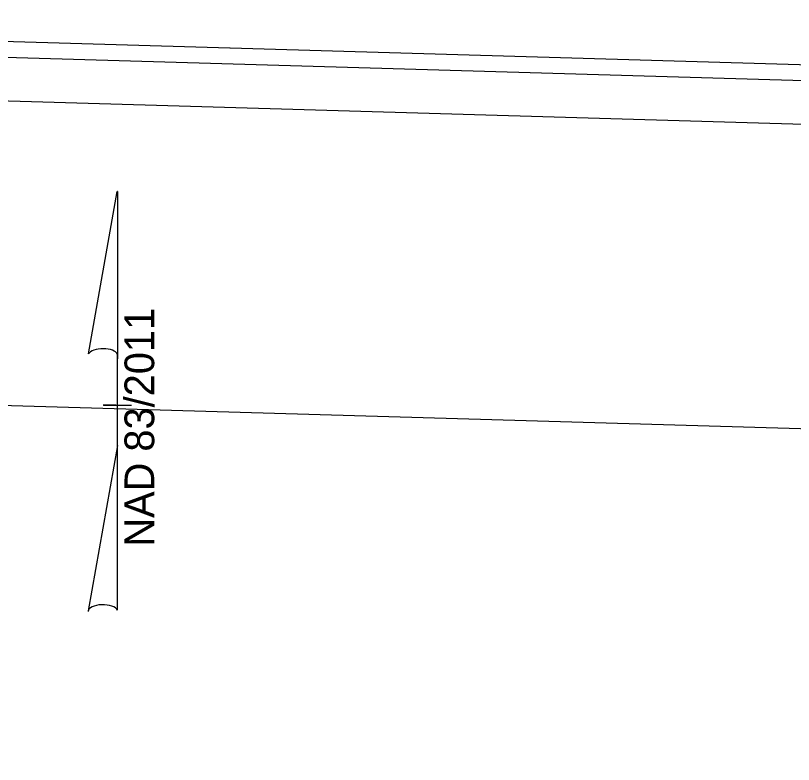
# Model space of a CAD drawing. Extents: x 2096999 to 2102576, y 682920 to 687015.
# Drawn here: x 2097306.6 to 2097529, y 686627 to 686841 of the extents above; entities that cross this region are included whole.
import ezdxf

# ---------------------------------------------------------------- set-up
doc = ezdxf.new("R2010")
doc.units = 0
for name, color, linetype in [('Default', 7, 'Continuous'), ('Scratch_Level_2', 7, 'Continuous'), ('Sheet Plan CELL', 7, 'Continuous'), ('Sheet Plot Border Inside CELL', 7, 'Continuous'), ('Sheet Plot Border Outside CELL', 7, 'Continuous')]:
    doc.layers.add(name, color=color, linetype=linetype)

msp = doc.modelspace()

# ---------------------------------------------------------------- linework, layer by layer
at = {"layer": 'Default'}
for p, q in [((2097327.5, 686744.36), (2097335.7, 686790.71)), ((2097335.75, 686790.71), (2097335.7, 686790.71)), ((2097335.75, 686790.71), (2097335.7, 686790.71)), ((2097335.75, 686790.71), (2097335.75, 686742.91)), ((2097335.75, 686718.11), (2097335.75, 686744.31)), ((2097335.75, 686742.91), (2097335.75, 686744.26)), ((2097331.75, 686729.71), (2097331.7, 686729.71)), ((2097335.3, 686729.71), (2097331.75, 686729.71)), ((2097331.8, 686729.71), (2097339.8, 686729.71)), ((2097335.75, 686718.11), (2097327.4, 686670.86)), ((2097335.8, 686671.06), (2097335.75, 686718.11))]:
    msp.add_line(p, q, dxfattribs=at)
for centre, start_param, end_param in [((2097331.64, 686743.86), 0.216388, 2.908219), ((2097331.64, 686670.69), 0.201328, 3.141593)]:
    msp.add_ellipse(centre, major_axis=(4.23, -0.03), ratio=0.461098, start_param=start_param, end_param=end_param, dxfattribs=at)
at = {"layer": 'Scratch_Level_2'}
msp.add_lwpolyline([(2097234.32, 685317.78), (2097026.76, 685323.81), (2097058.72, 686423.24), (2097059.31, 686437.01), (2097065.14, 686636.69), (2097214.22, 686632.33), (2097231.8, 686631.82), (2097295.87, 686629.95), (2097298.79, 686729.78), (2098044.58, 686708.09), (2098037.23, 686456.47), (2098110.07, 686454.34), (2098090.85, 685704.42)], close=True, dxfattribs=at)
at = {"layer": 'Sheet Plan CELL'}
msp.add_lwpolyline([(2097070.6, 686823.38), (2097026.77, 685323.98), (2098076.32, 685293.3), (2098120.15, 686792.67)], close=True, dxfattribs=at)
msp.add_lwpolyline([(2097070.6, 686823.38), (2097026.77, 685323.98), (2098076.32, 685293.3), (2098120.15, 686792.67)], close=True, dxfattribs=at)
at = {"layer": 'Sheet Plot Border Inside CELL'}
msp.add_lwpolyline([(2098074.34, 685139.8), (2098123.02, 686805.08), (2097068.48, 686835.92), (2097019.79, 685170.63)], close=True, dxfattribs=at)
msp.add_lwpolyline([(2098074.34, 685139.8), (2098123.02, 686805.08), (2097068.48, 686835.92), (2097019.79, 685170.63)], close=True, dxfattribs=at)
at = {"layer": 'Sheet Plot Border Outside CELL'}
msp.add_lwpolyline([(2098093.96, 685126.22), (2098143.15, 686809.01), (2097048.62, 686841), (2096999.42, 685158.22)], close=True, dxfattribs=at)
msp.add_lwpolyline([(2098093.96, 685126.22), (2098143.15, 686809.01), (2097048.62, 686841), (2096999.42, 685158.22)], close=True, dxfattribs=at)

# ---------------------------------------------------------------- texts
at = {"layer": 'Default'}
msp.add_text('NAD 83/2011', height=8.5, rotation=90, dxfattribs=at).set_placement((2097346.27, 686689.24))

doc.saveas('drawing.dxf')
